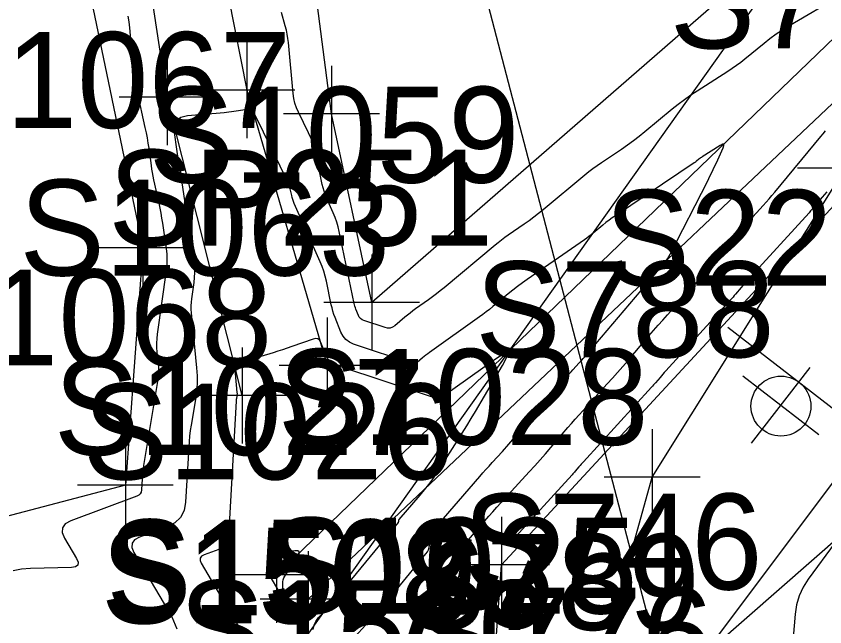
# Model space of a CAD drawing. Extents: x 816928 to 825690, y 436959 to 448212.
# Drawn here: x 818945.7 to 818979.44, y 445204.64 to 445230.11 of the extents above; entities that cross this region are included whole.
import ezdxf

# ---------------------------------------------------------------- set-up
doc = ezdxf.new("R2010")
doc.units = 0
for name, color, linetype in [('SURVEY - CONTOURS - Index with Text', 7, 'Continuous'), ('SURVEY - CONTOURS - Intermediate with optional Text', 7, 'Continuous'), ('SURVEY - DRAINAGE - Bridges Text', 7, 'Continuous'), ('SURVEY - DTM - Breaklines', 7, 'Continuous'), ('SURVEY - DTM - Breaklines - Points - Locators', 7, 'Continuous'), ('SURVEY - DTM - Breaklines - Points - Numbers', 7, 'Continuous'), ('SURVEY - PROPERTY - Parcels', 7, 'Continuous'), ('SURVEY - PROPERTY - ROW Lines', 7, 'Continuous'), ('SURVEY - ROADSIDE BARRIERS - Points - Numbers', 7, 'Continuous'), ('SURVEY - TRAFFIC CONTROL - Signs - Points - Locators', 7, 'Continuous'), ('SURVEY - TRAFFIC CONTROL - Signs - Points - Numbers', 7, 'Continuous'), ('SURVEY - TRAFFIC CONTROL - Signs and Devices with Text', 7, 'Continuous'), ('SURVEY - UTILITIES - Gas - Points - Numbers', 7, 'Continuous'), ('SURVEY - UTILITIES - Gas with Text', 7, 'Continuous'), ('SURVEY - UTILITIES - Telephone (Underground) - Points - Locators', 7, 'Continuous'), ('SURVEY - UTILITIES - Telephone (Underground) - Points - Numbers', 7, 'Continuous'), ('SURVEY - UTILITIES - Telephone (Underground) with Text', 7, 'Continuous'), ('SURVEY - UTILITIES - Water - Points - Numbers', 7, 'Continuous'), ('SURVEY - UTILITIES - Water with Text', 7, 'Continuous')]:
    doc.layers.add(name, color=color, linetype=linetype)

msp = doc.modelspace()

# ---------------------------------------------------------------- linework, layer by layer
at = {"layer": 'SURVEY - CONTOURS - Index with Text'}
msp.add_lwpolyline([(818979.518, 445222.782), (818979.425, 445222.674), (818979.335, 445222.566), (818979.04, 445222.21), (818978.976, 445222.134), (818978.911, 445222.059), (818978.846, 445221.984), (818978.78, 445221.911), (818976.242, 445219.126), (818976.167, 445219.044), (818976.094, 445218.96), (818976.021, 445218.876), (818975.949, 445218.791), (818975.715, 445218.513), (818975.664, 445218.454), (818975.613, 445218.395), (818975.561, 445218.337), (818975.509, 445218.279), (818972.801, 445215.31), (818972.741, 445215.244), (818972.682, 445215.177), (818972.623, 445215.11), (818972.565, 445215.042), (818972.376, 445214.82), (818972.335, 445214.772), (818972.294, 445214.725), (818972.252, 445214.678), (818972.21, 445214.632), (818969.375, 445211.525), (818969.326, 445211.472), (818969.278, 445211.417), (818969.23, 445211.363), (818969.182, 445211.308), (818969.028, 445211.128), (818968.994, 445211.089), (818968.961, 445211.051), (818968.927, 445211.013), (818968.893, 445210.976), (818966.38, 445208.224)], dxfattribs=at)
at = {"layer": 'SURVEY - CONTOURS - Intermediate with optional Text'}
for points in [[(818980.118, 445230.994), (818977.936, 445229.697), (818977.668, 445229.531), (818977.407, 445229.355), (818977.152, 445229.169), (818976.904, 445228.973), (818976.105, 445228.318), (818975.932, 445228.18), (818975.756, 445228.048), (818975.575, 445227.921), (818975.39, 445227.799), (818974.119, 445226.988), (818973.849, 445226.81), (818973.586, 445226.624), (818973.328, 445226.43), (818973.076, 445226.228), (818971.937, 445225.287), (818971.697, 445225.094), (818971.453, 445224.907), (818971.205, 445224.727), (818970.952, 445224.553), (818970.117, 445223.994), (818969.94, 445223.872), (818969.766, 445223.745), (818969.595, 445223.614), (818969.428, 445223.479), (818967.69, 445222.035), (818967.497, 445221.879), (818967.301, 445221.726), (818967.102, 445221.579), (818966.9, 445221.435), (818966.233, 445220.973), (818966.091, 445220.872), (818965.952, 445220.768), (818965.815, 445220.662), (818965.68, 445220.552), (818963.556, 445218.781), (818963.399, 445218.652), (818963.239, 445218.526), (818963.076, 445218.403), (818962.911, 445218.283), (818962.369, 445217.897), (818962.253, 445217.814), (818962.14, 445217.728), (818962.028, 445217.639), (818961.918, 445217.549), (818961.496, 445217.196), (818961.403, 445217.135), (818961.304, 445217.101), (818961.201, 445217.096), (818961.091, 445217.119), (818960.209, 445217.414), (818960.133, 445217.448), (818960.069, 445217.495), (818960.018, 445217.556), (818959.98, 445217.63), (818959.875, 445217.893), (818959.854, 445217.95), (818959.836, 445218.008), (818959.819, 445218.066), (818959.806, 445218.125), (818959.182, 445221.122), (818959.134, 445221.325), (818959.076, 445221.524), (818959.007, 445221.719), (818958.928, 445221.912), (818958.652, 445222.534), (818958.596, 445222.669), (818958.548, 445222.806), (818958.507, 445222.945), (818958.474, 445223.087), (818958.231, 445224.268), (818958.171, 445224.519), (818958.096, 445224.764), (818958.005, 445225.005), (818957.9, 445225.24), (818957.479, 445226.103), (818957.398, 445226.291), (818957.335, 445226.483), (818957.289, 445226.681), (818957.261, 445226.884), (818957.064, 445229.006), (818957.043, 445229.183), (818957.014, 445229.358), (818956.977, 445229.532), (818956.932, 445229.705), (818956.771, 445230.266)], [(818950.365, 445230.114), (818950.399, 445229.873), (818950.426, 445229.63), (818950.56, 445228.177), (818950.594, 445227.867), (818950.637, 445227.557), (818950.69, 445227.25), (818950.752, 445226.944), (818951.077, 445225.463), (818951.122, 445225.248), (818951.163, 445225.032), (818951.2, 445224.815), (818951.232, 445224.598), (818951.331, 445223.887), (818951.353, 445223.735), (818951.379, 445223.583), (818951.407, 445223.432), (818951.438, 445223.281), (818951.65, 445222.313), (818951.694, 445222.105), (818951.734, 445221.896), (818951.77, 445221.687), (818951.803, 445221.477), (818951.961, 445220.413), (818951.986, 445220.185), (818951.995, 445219.957), (818951.988, 445219.729), (818951.964, 445219.501), (818951.591, 445216.851), (818951.57, 445216.663), (818951.561, 445216.475), (818951.562, 445216.286), (818951.575, 445216.097), (818951.635, 445215.479), (818951.644, 445215.347), (818951.643, 445215.215), (818951.634, 445215.084), (818951.617, 445214.952), (818951.019, 445211.369), (818950.997, 445211.23), (818950.98, 445211.09), (818950.966, 445210.95), (818950.956, 445210.809), (818950.93, 445210.348), (818950.913, 445210.257), (818950.875, 445210.183), (818950.815, 445210.124), (818950.733, 445210.082), (818947.98, 445209.053), (818947.754, 445208.929), (818947.636, 445208.767), (818947.626, 445208.567), (818947.724, 445208.328), (818948.22, 445207.486), (818948.287, 445207.328), (818948.275, 445207.213), (818948.185, 445207.142), (818948.015, 445207.114), (818946.297, 445207.066), (818945.933, 445207.037), (818945.578, 445206.97)], [(818958.916, 445203.22), (818960.445, 445204.886), (818960.744, 445205.217), (818961.039, 445205.551), (818961.328, 445205.89), (818961.613, 445206.232), (818962.801, 445207.681), (818962.86, 445207.763), (818962.904, 445207.852), (818962.933, 445207.946), (818962.949, 445208.046), (818962.976, 445208.382), (818962.987, 445208.452), (818963.008, 445208.518), (818963.04, 445208.579), (818963.082, 445208.636), (818965.048, 445210.91), (818965.175, 445211.056), (818965.303, 445211.201), (818965.432, 445211.345), (818965.561, 445211.488), (818965.987, 445211.954), (818966.078, 445212.054), (818966.168, 445212.155), (818966.257, 445212.257), (818966.346, 445212.359), (818968.622, 445215.01), (818968.698, 445215.099), (818968.776, 445215.187), (818968.854, 445215.275), (818968.933, 445215.362), (818969.191, 445215.645), (818969.246, 445215.706), (818969.301, 445215.767), (818969.355, 445215.829), (818969.409, 445215.892), (818972.249, 445219.229), (818972.262, 445219.244), (818972.275, 445219.259), (818972.288, 445219.274), (818972.301, 445219.289), (818972.345, 445219.337), (818972.354, 445219.347), (818972.364, 445219.358), (818972.373, 445219.368), (818972.382, 445219.379), (818972.735, 445219.798), (818972.807, 445219.89), (818972.875, 445219.985), (818972.937, 445220.084), (818972.993, 445220.187), (818974.556, 445223.247), (818974.649, 445223.432), (818974.741, 445223.619), (818974.829, 445223.806), (818974.916, 445223.994), (818975.196, 445224.612), (818975.233, 445224.718), (818975.225, 445224.771), (818975.17, 445224.772), (818975.071, 445224.72), (818974.323, 445224.243), (818974.289, 445224.22), (818974.255, 445224.196), (818974.222, 445224.172), (818974.19, 445224.146), (818974.086, 445224.06), (818974.064, 445224.042), (818974.041, 445224.025), (818974.018, 445224.008), (818973.994, 445223.991), (818970.7, 445221.786), (818970.567, 445221.694), (818970.436, 445221.599), (818970.307, 445221.5), (818970.181, 445221.398), (818969.774, 445221.06), (818969.686, 445220.988), (818969.596, 445220.918), (818969.505, 445220.851), (818969.413, 445220.785), (818967.028, 445219.132), (818966.822, 445218.986), (818966.619, 445218.835), (818966.421, 445218.681), (818966.225, 445218.521), (818965.592, 445217.993), (818965.455, 445217.881), (818965.317, 445217.772), (818965.176, 445217.666), (818965.033, 445217.562), (818962.946, 445216.078), (818962.872, 445216.024), (818962.8, 445215.969), (818962.728, 445215.913), (818962.657, 445215.855), (818962.429, 445215.663), (818962.378, 445215.63), (818962.325, 445215.612), (818962.268, 445215.609), (818962.209, 445215.622), (818959.779, 445216.432), (818959.604, 445216.511), (818959.458, 445216.62), (818959.34, 445216.76), (818959.252, 445216.931), (818959.011, 445217.538), (818958.962, 445217.669), (818958.919, 445217.802), (818958.882, 445217.937), (818958.85, 445218.073), (818958.646, 445219.054), (818958.597, 445219.263), (818958.537, 445219.468), (818958.466, 445219.669), (818958.384, 445219.867), (818957.306, 445222.296), (818957.272, 445222.377), (818957.243, 445222.46), (818957.218, 445222.545), (818957.198, 445222.63), (818957.14, 445222.913), (818957.126, 445222.973), (818957.108, 445223.032), (818957.086, 445223.089), (818957.061, 445223.145), (818955.679, 445225.984), (818955.605, 445226.097), (818955.51, 445226.171), (818955.395, 445226.207), (818955.259, 445226.204), (818954.784, 445226.133), (818954.682, 445226.118), (818954.58, 445226.105), (818954.478, 445226.094), (818954.375, 445226.084), (818952.851, 445225.953), (818952.578, 445225.89), (818952.395, 445225.754), (818952.302, 445225.545), (818952.301, 445225.264), (818952.494, 445223.869), (818952.5, 445223.826), (818952.508, 445223.783), (818952.516, 445223.741), (818952.525, 445223.698), (818952.555, 445223.56), (818952.561, 445223.53), (818952.567, 445223.501), (818952.572, 445223.471), (818952.577, 445223.441), (818953.11, 445219.832), (818953.134, 445219.624), (818953.142, 445219.416), (818953.135, 445219.208), (818953.113, 445219), (818953.018, 445218.319), (818953.002, 445218.174), (818952.994, 445218.027), (818952.995, 445217.881), (818953.005, 445217.735), (818953.228, 445215.441), (818953.249, 445215.111), (818953.249, 445214.781), (818953.227, 445214.453), (818953.183, 445214.125), (818953.004, 445213.055), (818952.969, 445212.826), (818952.94, 445212.596), (818952.917, 445212.365), (818952.901, 445212.133), (818952.77, 445209.839), (818952.706, 445209.49), (818952.559, 445209.202), (818952.328, 445208.976), (818952.013, 445208.812), (818950.848, 445208.377), (818950.646, 445208.267), (818950.541, 445208.122), (818950.532, 445207.944), (818950.619, 445207.731), (818952.2, 445205.053), (818952.413, 445204.549)], [(818958.79, 445200.635), (818962.81, 445205.015), (818962.977, 445205.199), (818963.141, 445205.386), (818963.303, 445205.575), (818963.463, 445205.767), (818963.978, 445206.396), (818964.077, 445206.535), (818964.151, 445206.685), (818964.201, 445206.844), (818964.228, 445207.013), (818964.28, 445207.669), (818964.302, 445207.805), (818964.344, 445207.933), (818964.405, 445208.053), (818964.488, 445208.164), (818965.259, 445209.056), (818965.425, 445209.247), (818965.592, 445209.436), (818965.76, 445209.624), (818965.93, 445209.812), (818967.112, 445211.106), (818967.338, 445211.355), (818967.562, 445211.606), (818967.784, 445211.858), (818968.004, 445212.113), (818968.719, 445212.946), (818968.873, 445213.124), (818969.028, 445213.301), (818969.185, 445213.477), (818969.343, 445213.651), (818970.362, 445214.767), (818970.579, 445215.007), (818970.794, 445215.249), (818971.007, 445215.493), (818971.218, 445215.739), (818972.1, 445216.775), (818972.29, 445216.996), (818972.482, 445217.216), (818972.675, 445217.433), (818972.871, 445217.65), (818973.654, 445218.508), (818973.82, 445218.693), (818973.985, 445218.879), (818974.148, 445219.067), (818974.31, 445219.257), (818975.62, 445220.814), (818975.787, 445221.011), (818975.957, 445221.207), (818976.129, 445221.401), (818976.302, 445221.593), (818976.872, 445222.219), (818976.994, 445222.353), (818977.113, 445222.489), (818977.231, 445222.627), (818977.348, 445222.766), (818979.274, 445225.091), (818979.371, 445225.206), (818979.469, 445225.321)], [(818958.092, 445204.52), (818958.129, 445204.699), (818958.205, 445204.865), (818958.32, 445205.019), (818958.761, 445205.498), (818958.854, 445205.602), (818958.947, 445205.707), (818959.037, 445205.813), (818959.127, 445205.92), (818961.648, 445208.995), (818961.656, 445209.005), (818961.661, 445209.017), (818961.665, 445209.029), (818961.667, 445209.041), (818961.67, 445209.084), (818961.672, 445209.093), (818961.675, 445209.101), (818961.679, 445209.109), (818961.684, 445209.116), (818962.556, 445210.125), (818962.739, 445210.345), (818962.914, 445210.57), (818963.08, 445210.802), (818963.238, 445211.039), (818964.125, 445212.425), (818964.314, 445212.722), (818964.5, 445213.022), (818964.683, 445213.323), (818964.864, 445213.626), (818965.99, 445215.537), (818966.153, 445215.861), (818966.159, 445216.014), (818966.007, 445215.995), (818965.698, 445215.805), (818963.494, 445214.237), (818963.477, 445214.225), (818963.459, 445214.211), (818963.442, 445214.198), (818963.425, 445214.184), (818963.37, 445214.138), (818963.358, 445214.13), (818963.345, 445214.125), (818963.331, 445214.125), (818963.317, 445214.128), (818959.084, 445215.539), (818958.932, 445215.607), (818958.806, 445215.702), (818958.704, 445215.823), (818958.627, 445215.971), (818958.418, 445216.497), (818958.365, 445216.591), (818958.294, 445216.646), (818958.206, 445216.664), (818958.1, 445216.642), (818957.198, 445216.326), (818957.004, 445216.259), (818956.81, 445216.195), (818956.615, 445216.132), (818956.419, 445216.071), (818955.159, 445215.686), (818955.006, 445215.615), (818954.902, 445215.512), (818954.846, 445215.376), (818954.84, 445215.208), (818954.916, 445214.418), (818954.919, 445214.382), (818954.919, 445214.345), (818954.916, 445214.309), (818954.911, 445214.273), (818954.892, 445214.154), (818954.888, 445214.129), (818954.884, 445214.103), (818954.882, 445214.078), (818954.88, 445214.052), (818954.557, 445208.409), (818954.524, 445208.224), (818954.446, 445208.072), (818954.324, 445207.953), (818954.157, 445207.866), (818953.541, 445207.636), (818953.435, 445207.578), (818953.379, 445207.501), (818953.375, 445207.407), (818953.421, 445207.295), (818956.152, 445202.668)], [(818979.869, 445208.154), (818978.749, 445206.626), (818978.535, 445206.288), (818978.372, 445205.932), (818978.26, 445205.556), (818978.2, 445205.161), (818978.033, 445203.213)], [(818957.327, 445207.806), (818956.62, 445207.737), (818956.517, 445207.712), (818956.442, 445207.661), (818956.394, 445207.584), (818956.373, 445207.48), (818956.345, 445206.978), (818956.341, 445206.958), (818956.333, 445206.942), (818956.319, 445206.929), (818956.301, 445206.92), (818956.235, 445206.895), (818956.224, 445206.889), (818956.218, 445206.881), (818956.217, 445206.87), (818956.222, 445206.858), (818956.727, 445206.003), (818956.781, 445205.926), (818956.818, 445205.906), (818956.838, 445205.943), (818956.842, 445206.036), (818956.828, 445206.434), (818956.831, 445206.518), (818956.847, 445206.598), (818956.875, 445206.674), (818956.915, 445206.747), (818957.463, 445207.581), (818957.517, 445207.691), (818957.513, 445207.765), (818957.449, 445207.803), (818957.327, 445207.806)]]:
    msp.add_lwpolyline(points, dxfattribs=at)
at = {"layer": 'SURVEY - DRAINAGE - Bridges Text'}
msp.add_lwpolyline([(818964.904, 445232.428), (818977.092, 445185.746)], dxfattribs=at)
at = {"layer": 'SURVEY - DTM - Breaklines'}
for points in [[(818956.561, 445206.805), (818988.908, 445237.973), (818996.006, 445243.104), (819004.505, 445254.331), (819023.094, 445280.216), (819052.334, 445321.974), (819079.91, 445358.328), (819102.597, 445391.707)], [(818957.887, 445205.786), (818990.182, 445236.343), (818997.6, 445242.102), (819006.167, 445253.219), (819054.017, 445320.891), (819080.835, 445357.817), (819104.169, 445390.571)], [(818964.92, 445195.492), (818965.449, 445200.19), (818965.951, 445207.228), (818985.491, 445228.351), (818993.217, 445232.84), (818999.097, 445239.365), (819007.192, 445250.479), (819027.405, 445276.904), (819055.511, 445319.799), (819082.413, 445356.886)], [(819073.298, 445355.122), (819048.115, 445322.006), (819023.42, 445284.723), (818992.563, 445243.615), (818984.238, 445238.804), (818960.537, 445218.165), (818958.862, 445226.04), (818957.684, 445235.166), (818941.199, 445267.453), (818950.993, 445220.447), (818950.259, 445210.542), (818939.42, 445207.694)], [(818955.127, 445214.291), (818952.003, 445226.736), (818950.052, 445239.527), (818945.78, 445254.112), (818953.794, 445234.774), (818955.325, 445227.021), (818958.675, 445215.535)]]:
    msp.add_lwpolyline(points, dxfattribs=at)
at = {"layer": 'SURVEY - DTM - Breaklines - Points - Locators'}
for p, q in [((818952.003, 445228.736), (818952.003, 445224.736)), ((818955.325, 445229.021), (818955.325, 445225.021)), ((818958.862, 445228.04), (818958.862, 445224.04)), ((818957.325, 445227.021), (818953.325, 445227.021)), ((818954.003, 445226.736), (818950.003, 445226.736)), ((818960.862, 445226.04), (818956.862, 445226.04)), ((818950.993, 445222.447), (818950.993, 445218.447)), ((818952.993, 445220.447), (818948.993, 445220.447)), ((818960.537, 445220.165), (818960.537, 445216.165)), ((818962.537, 445218.165), (818958.537, 445218.165)), ((818958.675, 445217.535), (818958.675, 445213.535)), ((818955.127, 445216.291), (818955.127, 445212.291)), ((818960.675, 445215.535), (818956.675, 445215.535)), ((818957.127, 445214.291), (818953.127, 445214.291)), ((818950.259, 445212.542), (818950.259, 445208.542)), ((818952.259, 445210.542), (818948.259, 445210.542)), ((818965.951, 445209.228), (818965.951, 445205.228)), ((818956.561, 445208.805), (818956.561, 445204.805)), ((818957.887, 445207.786), (818957.887, 445203.786)), ((818967.951, 445207.228), (818963.951, 445207.228)), ((818958.561, 445206.805), (818954.561, 445206.805)), ((818959.887, 445205.786), (818955.887, 445205.786))]:
    msp.add_line(p, q, dxfattribs=at)
at = {"layer": 'SURVEY - PROPERTY - Parcels'}
msp.add_line((818939.168, 445178.006), (819170.276, 445503.188), dxfattribs=at)
at = {"layer": 'SURVEY - PROPERTY - ROW Lines'}
msp.add_line((818939.168, 445178.006), (819182.874, 445520.914), dxfattribs=at)
at = {"layer": 'SURVEY - TRAFFIC CONTROL - Signs - Points - Locators'}
for p, q in [((818976.383, 445212.294), (818978.831, 445215.458)), ((818979.189, 445212.652), (818976.025, 445215.1))]:
    msp.add_line(p, q, dxfattribs=at)
at = {"layer": 'SURVEY - TRAFFIC CONTROL - Signs and Devices with Text'}
msp.add_line((818975.391, 445217.139), (818981.322, 445212.55), dxfattribs=at)
msp.add_circle((818977.609, 445213.843), 1.25, dxfattribs=at)
at = {"layer": 'SURVEY - UTILITIES - Gas with Text'}
msp.add_lwpolyline([(818968.105, 445195.328), (818969.738, 445197.267), (819012.001, 445253.658), (819064.107, 445326.037), (819122.078, 445408.8), (819183.152, 445497.068), (819237.635, 445568.809), (819293.129, 445639.42), (819349.073, 445723.122), (819383.091, 445785.202)], dxfattribs=at)
at = {"layer": 'SURVEY - UTILITIES - Telephone (Underground) - Points - Locators'}
for p, q in [((818982.303, 445223.767), (818978.303, 445223.767)), ((818972.238, 445212.883), (818972.238, 445208.883)), ((818974.238, 445210.883), (818970.238, 445210.883))]:
    msp.add_line(p, q, dxfattribs=at)
at = {"layer": 'SURVEY - UTILITIES - Telephone (Underground) with Text'}
msp.add_lwpolyline([(818930.857, 445150.66), (818932.992, 445149.937), (818944.966, 445166.651), (818949.519, 445169.463), (818968.39, 445195.328), (818969.083, 445199.507), (818972.238, 445210.883), (818980.303, 445223.767), (818989.561, 445238.187), (819000.76, 445253.257)], dxfattribs=at)
at = {"layer": 'SURVEY - UTILITIES - Water with Text'}
msp.add_lwpolyline([(818803.235, 444799.745), (818822.09, 444847.157), (818840.807, 444894.989), (818859.419, 444943.113), (818878.417, 444989.731), (818897.247, 445035.659), (818918.394, 445078.737), (818943.016, 445121.017), (818943.424, 445156.253), (818947.564, 445166.115), (818971.795, 445201.192), (819041.117, 445261.897), (819085.564, 445324.056), (819114.437, 445364.745), (819142.589, 445406.123), (819261.281, 445567.542), (819325.961, 445650.567), (819357.336, 445697.813), (819381.766, 445739.87), (819404.905, 445782.998)], dxfattribs=at)

# ---------------------------------------------------------------- texts
at = {"layer": 'SURVEY - CONTOURS - Index with Text'}
msp.add_text('310', height=5, rotation=251.7422, dxfattribs=at).set_placement((818963.576, 445208.918))
at = {"layer": 'SURVEY - DTM - Breaklines - Points - Numbers'}
for s, p in [('S1067', (818941.705, 445225.447)), ('S1059', (818951.234, 445223.165)), ('SP251', (818949.545, 445220.535)), ('S1063', (818945.839, 445219.291)), ('S1068', (818940.924, 445215.542)), ('S1028', (818956.616, 445212.228)), ('S1027', (818947.273, 445211.805)), ('S1026', (818948.489, 445210.786)), ('S1025', (818956.161, 445205.19)), ('S1508', (818949.239, 445204.778))]:
    msp.add_text(s, height=4, dxfattribs=at).set_placement(p)
at = {"layer": 'SURVEY - ROADSIDE BARRIERS - Points - Numbers'}
for s, p in [('S1509', (818949.461, 445205.111)), ('S1510', (818952.489, 445202.578))]:
    msp.add_text(s, height=4, dxfattribs=at).set_placement(p)
at = {"layer": 'SURVEY - TRAFFIC CONTROL - Signs - Points - Numbers'}
msp.add_text('S222', height=4, dxfattribs=at).set_placement((818970.244, 445218.863))
at = {"layer": 'SURVEY - UTILITIES - Gas - Points - Numbers'}
msp.add_text('S776', height=4, dxfattribs=at).set_placement((818962.292, 445202.267))
at = {"layer": 'SURVEY - UTILITIES - Telephone (Underground) - Points - Numbers'}
for s, p in [('S787', (818972.967, 445228.767)), ('S788', (818964.855, 445215.883)), ('S789', (818961.731, 445204.507))]:
    msp.add_text(s, height=4, dxfattribs=at).set_placement(p)
at = {"layer": 'SURVEY - UTILITIES - Water - Points - Numbers'}
msp.add_text('S746', height=4, dxfattribs=at).set_placement((818964.349, 445206.192))

doc.saveas('drawing.dxf')
